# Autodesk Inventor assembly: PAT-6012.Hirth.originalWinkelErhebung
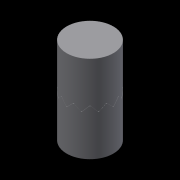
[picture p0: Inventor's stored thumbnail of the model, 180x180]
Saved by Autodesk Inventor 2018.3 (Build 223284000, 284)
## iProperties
Created: 2020-03
Part Number: PAT-6012.Hirth.originalWinkelErhebung
Document SubType Name: Assembly
Designer: Th. Mörgeli
Mass: 35.273 g
Surface Area: 96.6276 cm^2
Volume: 35.273 cm^3
Density: 1 g/cm^3
Author: Th. Mörgeli
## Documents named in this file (2)
- C:\Users\mothomas\Documents\Inventor\Patterson\PATHirth.originalWinkelErhebung.iam
- C:\Users\mothomas\Documents\Inventor\Patterson\PATHirth.originalWinkelErhebung.ipt
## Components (2 placed, 1 different names)
1. PATHirth.originalWinkelErhebung:1 — Mate:1, Mate:2, Angle:1
2. PATHirth.originalWinkelErhebung:2 — Mate:1, Mate:2, Angle:1
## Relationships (3: Mate 2, Angle 1)
- Mate:1: PATHirth.originalWinkelErhebung:1 ↔ PATHirth.originalWinkelErhebung:2
- Mate:2: PATHirth.originalWinkelErhebung:1 ↔ PATHirth.originalWinkelErhebung:2
- Angle:1: PATHirth.originalWinkelErhebung:1 ↔ PATHirth.originalWinkelErhebung:2
